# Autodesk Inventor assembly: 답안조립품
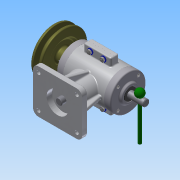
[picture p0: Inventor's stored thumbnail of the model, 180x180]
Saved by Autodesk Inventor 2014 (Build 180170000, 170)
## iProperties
Created: 2015-12
Part Number: 답안조립품
Document SubType Name: Assembly
Designer: imci
Mass: 1938.75 g
Surface Area: 1487.05 cm^2
Volume: 469.721 cm^3
Density: 4.12744 g/cm^3
Author: imci
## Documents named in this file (19)
- C:\Users\imci\Desktop\351208V1040\답안조립품.iam
- C:\Users\imci\Desktop\351208V1040\본체.ipt
- C:\Users\imci\Desktop\351208V1040\V-벨트풀리.ipt
- C:\Users\imci\Desktop\351208V1040\너트 M4.ipt
- C:\Users\imci\Desktop\351208V1040\뒤커버.ipt
- C:\Users\imci\Desktop\351208V1040\레바.ipt
- C:\Users\imci\Desktop\351208V1040\멈춤나사 M3x8.ipt
- C:\Users\imci\Desktop\351208V1040\베어링 6201.ipt
- C:\Users\imci\Desktop\351208V1040\베어링 6202.ipt
- C:\Users\imci\Desktop\351208V1040\본체커버.ipt
- C:\Users\imci\Desktop\351208V1040\볼트 M3x0.5x8.ipt
- C:\Users\imci\Desktop\351208V1040\볼트 M4 x 16.ipt
- C:\Users\imci\Desktop\351208V1040\스프링.ipt
- C:\Users\imci\Desktop\351208V1040\슬라이드.ipt
- C:\Users\imci\Desktop\351208V1040\앞커버.ipt
- C:\Users\imci\Desktop\351208V1040\오일실 12 22 7.ipt
- C:\Users\imci\Desktop\351208V1040\와셔 ST 4-100.ipt
- C:\Users\imci\Desktop\351208V1040\키 4 x 4 x 18.ipt
- C:\Users\imci\Desktop\351208V1040\편심축.ipt
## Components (13 placed, 4 different names)
1. V-벨트풀리:1
2. ISO 4032 M4:1
3. ISO 4762 M4 x 16:1
4. ISO 7091 ST 4 - 100 HV:1
5. ISO 4032 M4:2
6. ISO 4762 M4 x 16:2
7. ISO 7091 ST 4 - 100 HV:2
8. ISO 4032 M4:3
9. ISO 4762 M4 x 16:3
10. ISO 7091 ST 4 - 100 HV:3
11. ISO 4032 M4:4
12. ISO 4762 M4 x 16:4
13. ISO 7091 ST 4 - 100 HV:4
